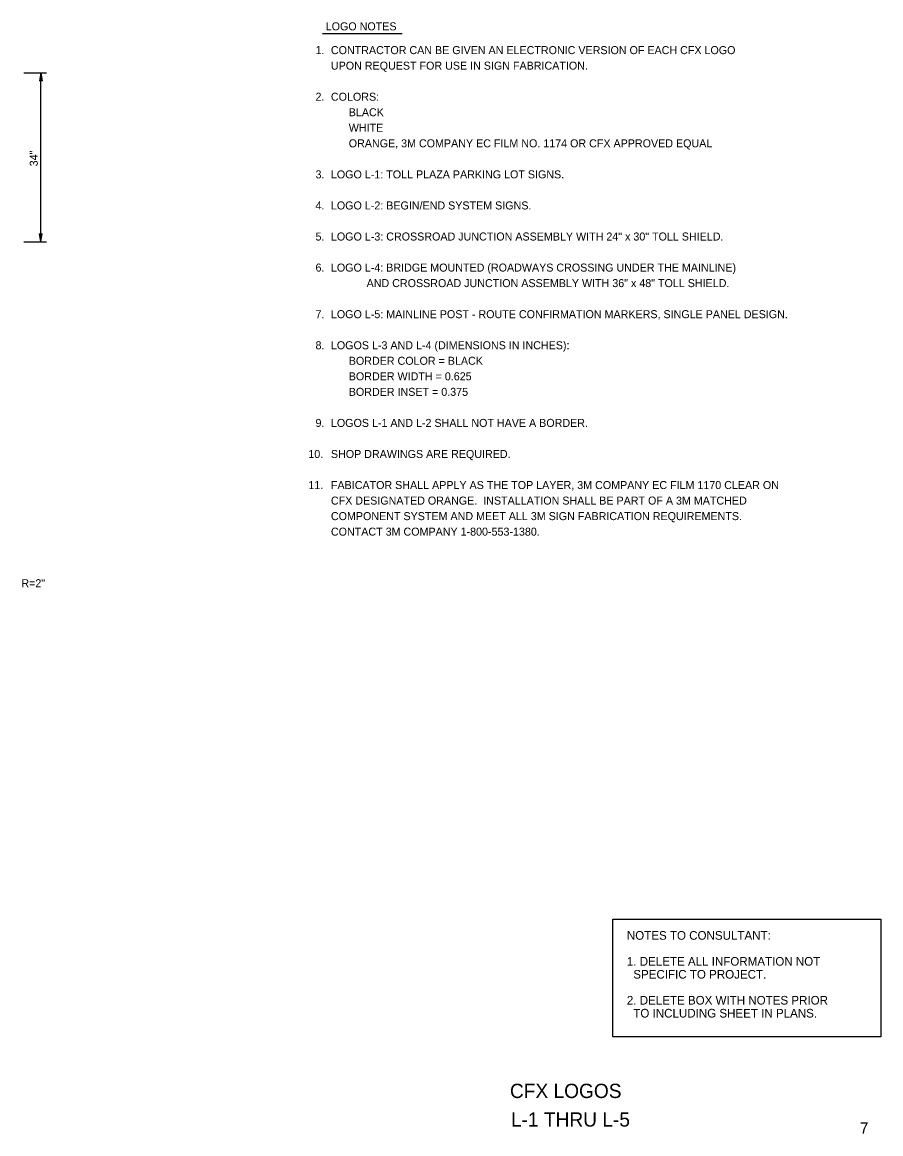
# Model space of a CAD drawing. Extents: x 60714 to 61343, y 7599 to 7998.
# Drawn here: x 61043.1 to 61343.3, y 7609.2 to 7998 of the extents above; entities that cross this region are included whole.
import ezdxf

# ---------------------------------------------------------------- set-up
doc = ezdxf.new("R2010")
doc.units = 0
for name, color, linetype in [('2', 7, 'Continuous'), ('21', 7, 'Continuous'), ('TextAlert', 7, 'Continuous'), ('TextMisc', 7, 'Continuous'), ('TextShtNo', 7, 'Continuous')]:
    doc.layers.add(name, color=color, linetype=linetype)

msp = doc.modelspace()

# ---------------------------------------------------------------- linework, layer by layer
at = {"layer": '2'}
for p, q in [((61148.08, 7993.97), (61175.94, 7993.97)), ((61043.58, 7980.26), (61051.58, 7980.26)), ((61049.58, 7921.12), (61049.58, 7980.26)), ((61043.58, 7921.12), (61051.58, 7921.12))]:
    msp.add_line(p, q, dxfattribs=at)
at = {"layer": '21'}
for p, q in [((61049.58, 7980.26), (61049.09, 7977.49)), ((61049.58, 7980.26), (61049.35, 7977.6)), ((61049.58, 7980.26), (61050.07, 7977.49)), ((61049.58, 7980.26), (61049.81, 7977.6)), ((61049.09, 7977.49), (61049.58, 7977.7)), ((61049.58, 7977.7), (61050.07, 7977.49)), ((61049.58, 7921.12), (61049.09, 7923.89)), ((61049.58, 7923.68), (61049.09, 7923.89)), ((61049.58, 7921.12), (61049.35, 7923.77)), ((61049.58, 7921.12), (61050.07, 7923.89)), ((61050.07, 7923.89), (61049.58, 7923.68)), ((61049.58, 7921.12), (61049.81, 7923.78))]:
    msp.add_line(p, q, dxfattribs=at)
at = {"layer": 'TextAlert'}
msp.add_lwpolyline([(61249.54, 7684.21), (61343.29, 7684.21), (61343.29, 7643.04), (61249.54, 7643.04)], close=True, dxfattribs=at)

# ---------------------------------------------------------------- texts
at = {"layer": '2'}
for s, p in [('LOGO NOTES', (61149.2, 7995.12)), ('R=2"', (61042.76, 7800.35))]:
    msp.add_text(s, height=2.8, dxfattribs=at).set_placement(p)
msp.add_text('34"', height=2.8, rotation=90, dxfattribs=at).set_placement((61048.49, 7947.55))
at = {"layer": '21'}
for s, p in [('1.', (61145.63, 7986.8)), ('CONTRACTOR CAN BE GIVEN AN ELECTRONIC VERSION OF EACH CFX LOGO', (61151.01, 7986.8)), ('UPON REQUEST FOR USE IN SIGN FABRICATION.', (61151.01, 7981.37)), ('2.', (61145.63, 7970.5)), ('COLORS:', (61151.01, 7970.5)), ('      BLACK', (61151.01, 7965.07)), ('      WHITE', (61151.01, 7959.64)), ('      ORANGE, 3M COMPANY EC FILM NO. 1174 OR CFX APPROVED EQUAL', (61151.01, 7954.2)), ('3.', (61145.63, 7943.34)), ('LOGO L-1: TOLL PLAZA PARKING LOT SIGNS.', (61151.01, 7943.34)), ('4.', (61145.63, 7932.47)), ('LOGO L-2: BEGIN/END SYSTEM SIGNS.', (61151.01, 7932.47)), ('5.', (61145.63, 7921.6)), ('LOGO L-3: CROSSROAD JUNCTION ASSEMBLY WITH 24" x 30" TOLL SHIELD.', (61151.01, 7921.61)), ('6.', (61145.63, 7910.74)), ('LOGO L-4: BRIDGE MOUNTED (ROADWAYS CROSSING UNDER THE MAINLINE)', (61151.01, 7910.74)), ('            AND CROSSROAD JUNCTION ASSEMBLY WITH 36" x 48" TOLL SHIELD.', (61151.01, 7905.31)), ('7.', (61145.63, 7894.44)), ('LOGO L-5: MAINLINE POST - ROUTE CONFIRMATION MARKERS, SINGLE PANEL DESIGN.', (61151.01, 7894.44)), ('8.', (61145.63, 7883.57)), ('LOGOS L-3 AND L-4 (DIMENSIONS IN INCHES):', (61151.01, 7883.57)), ('      BORDER COLOR = BLACK', (61151.01, 7878.14)), ('      BORDER WIDTH = 0.625', (61151.01, 7872.71)), ('      BORDER INSET = 0.375', (61151.01, 7867.28)), ('9. ', (61145.63, 7856.41)), ('LOGOS L-1 AND L-2 SHALL NOT HAVE A BORDER.', (61151.01, 7856.41)), ('10.', (61143.12, 7845.54)), ('SHOP DRAWINGS ARE REQUIRED.', (61151.01, 7845.54)), ('11.', (61143.12, 7834.68)), ('FABICATOR SHALL APPLY AS THE TOP LAYER, 3M COMPANY EC FILM 1170 CLEAR ON ', (61151.01, 7834.68)), ('CFX DESIGNATED ORANGE.  INSTALLATION SHALL BE PART OF A 3M MATCHED ', (61151.01, 7829.24)), ('COMPONENT SYSTEM AND MEET ALL 3M SIGN FABRICATION REQUIREMENTS.  ', (61151.01, 7823.81)), ('CONTACT 3M COMPANY 1-800-553-1380.', (61151.01, 7818.38))]:
    msp.add_text(s, height=2.8, dxfattribs=at).set_placement(p)
at = {"layer": 'TextAlert'}
for s, p in [('NOTES TO CONSULTANT:', (61254.51, 7677.04)), ('1. DELETE ALL INFORMATION NOT', (61254.51, 7667.97)), ('  SPECIFIC TO PROJECT.', (61254.51, 7663.44)), ('2. DELETE BOX WITH NOTES PRIOR', (61254.51, 7654.36)), ('  TO INCLUDING SHEET IN PLANS.', (61254.51, 7649.83))]:
    msp.add_text(s, height=3.024, dxfattribs=at).set_placement(p)
at = {"layer": 'TextMisc'}
for s, p in [('       CFX LOGOS        ', (61200.62, 7621.67)), ('      L-1 THRU L-5      ', (61202.83, 7611.67))]:
    msp.add_text(s, height=5, rotation=360, dxfattribs=at).set_placement(p)
at = {"layer": 'TextShtNo'}
msp.add_text('7', height=4, rotation=360, dxfattribs=at).set_placement((61336, 7609.17))

doc.saveas('drawing.dxf')
